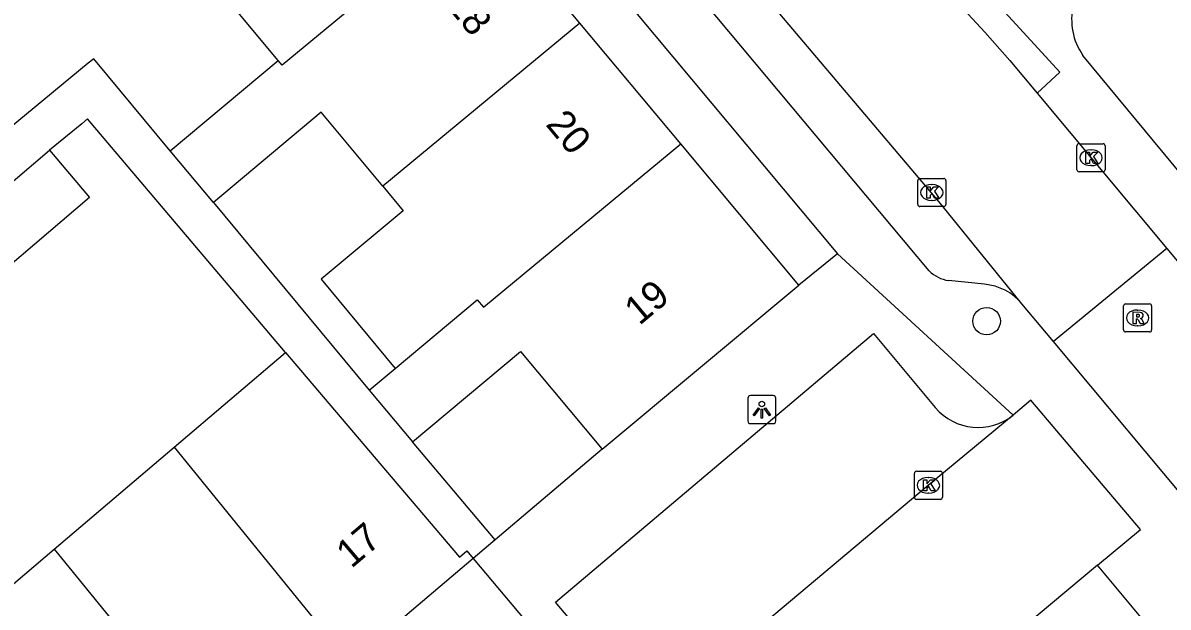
# Model space of a CAD drawing. Extents: x 160379 to 161131, y 383940 to 384849.
# Drawn here: x 160767.81 to 160808.59, y 384435.36 to 384456.14 of the extents above; entities that cross this region are included whole.
import ezdxf

# ---------------------------------------------------------------- set-up
doc = ezdxf.new("R2010")
doc.units = 0
for name, color, linetype in [('IMGEO_Boom', 7, 'Continuous'), ('IMGEO_Kolk', 7, 'Continuous'), ('IMGEO_Lichtpunt', 7, 'Continuous'), ('IMGEO_Muur', 7, 'Continuous'), ('IMGEO_Pand', 7, 'Continuous'), ('IMGEO_Pand_nummerreeks', 7, 'Continuous'), ('IMGEO_Rijbaan_lokaal_open', 7, 'Continuous'), ('IMGEO_Rioolput', 7, 'Continuous'), ('IMGEO_Voetpad_open', 7, 'Continuous')]:
    doc.layers.add(name, color=color, linetype=linetype)

msp = doc.modelspace()

# ---------------------------------------------------------------- linework, layer by layer
at = {"layer": 'IMGEO_Boom'}
msp.add_circle((160802.132, 384445.529), 0.489, dxfattribs=at)
at = {"layer": 'IMGEO_Kolk'}
for p, q in [((160805.349, 384450.917), (160805.349, 384451.769)), ((160805.424, 384451.843), (160806.276, 384451.843)), ((160806.35, 384451.769), (160806.35, 384450.917)), ((160805.837, 384451.623), (160805.862, 384451.623)), ((160805.86, 384451.063), (160805.835, 384451.063)), ((160799.68, 384449.681), (160799.68, 384450.533)), ((160799.755, 384450.607), (160800.607, 384450.607)), ((160800.681, 384450.533), (160800.681, 384449.681)), ((160806.276, 384450.843), (160805.424, 384450.843)), ((160800.168, 384450.387), (160800.193, 384450.387)), ((160800.191, 384449.827), (160800.166, 384449.827)), ((160800.607, 384449.607), (160799.755, 384449.607)), ((160799.558, 384439.264), (160799.558, 384440.116)), ((160799.633, 384440.19), (160800.485, 384440.19)), ((160800.046, 384439.97), (160800.071, 384439.97)), ((160800.559, 384440.116), (160800.559, 384439.264)), ((160800.485, 384439.19), (160799.633, 384439.19)), ((160800.069, 384439.41), (160800.044, 384439.41))]:
    msp.add_line(p, q, dxfattribs=at)
for points in [[(160805.349, 384450.917), (160805.349, 384451.769)], [(160805.424, 384451.843), (160806.276, 384451.843)], [(160806.35, 384451.769), (160806.35, 384450.917)], [(160805.67, 384451.543), (160805.793, 384451.543), (160805.793, 384451.392), (160805.923, 384451.543), (160806.087, 384451.543), (160805.941, 384451.392), (160806.094, 384451.143), (160805.942, 384451.143), (160805.857, 384451.307), (160805.793, 384451.24), (160805.793, 384451.143), (160805.67, 384451.143), (160805.67, 384451.543)], [(160799.68, 384449.681), (160799.68, 384450.533)], [(160799.755, 384450.607), (160800.607, 384450.607)], [(160800.681, 384450.533), (160800.681, 384449.681)], [(160806.276, 384450.843), (160805.424, 384450.843)], [(160800.001, 384450.307), (160800.124, 384450.307), (160800.124, 384450.156), (160800.254, 384450.307), (160800.418, 384450.307), (160800.272, 384450.156), (160800.425, 384449.907), (160800.273, 384449.907), (160800.188, 384450.071), (160800.124, 384450.004), (160800.124, 384449.907), (160800.001, 384449.907), (160800.001, 384450.307)], [(160800.607, 384449.607), (160799.755, 384449.607)], [(160799.558, 384439.264), (160799.558, 384440.116)], [(160799.633, 384440.19), (160800.485, 384440.19)], [(160799.879, 384439.89), (160800.002, 384439.89), (160800.002, 384439.739), (160800.132, 384439.89), (160800.296, 384439.89), (160800.15, 384439.739), (160800.303, 384439.49), (160800.151, 384439.49), (160800.066, 384439.654), (160800.002, 384439.587), (160800.002, 384439.49), (160799.879, 384439.49), (160799.879, 384439.89)], [(160800.559, 384440.116), (160800.559, 384439.264)], [(160800.485, 384439.19), (160799.633, 384439.19)]]:
    msp.add_lwpolyline(points, dxfattribs=at)
for centre, start, end in [((160805.426, 384451.767), 91.552, 178.448), ((160805.426, 384451.767), 91.552, 178.448), ((160806.274, 384451.767), 1.552, 88.448), ((160806.274, 384451.767), 1.552, 88.448), ((160805.426, 384450.919), 181.552, 268.448), ((160805.426, 384450.919), 181.552, 268.448), ((160806.274, 384450.919), 271.552, 358.448), ((160806.274, 384450.919), 271.552, 358.448), ((160799.757, 384450.531), 91.552, 178.448), ((160799.757, 384450.531), 91.552, 178.448), ((160800.605, 384450.531), 1.552, 88.448), ((160800.605, 384450.531), 1.552, 88.448), ((160799.757, 384449.683), 181.552, 268.448), ((160799.757, 384449.683), 181.552, 268.448), ((160800.605, 384449.683), 271.552, 358.448), ((160800.605, 384449.683), 271.552, 358.448), ((160799.635, 384440.114), 91.552, 178.448), ((160799.635, 384440.114), 91.552, 178.448), ((160800.483, 384440.114), 1.552, 88.448), ((160800.483, 384440.114), 1.552, 88.448), ((160799.635, 384439.266), 181.552, 268.448), ((160799.635, 384439.266), 181.552, 268.448), ((160800.483, 384439.266), 271.552, 358.448), ((160800.483, 384439.266), 271.552, 358.448)]:
    msp.add_arc(centre, 0.0765, start, end, dxfattribs=at)
for centre, major_axis, ratio, start_param, end_param in [((160805.836, 384451.343), (-0.387, 0.002), 0.722429, 4.712389, 7.853982), ((160805.861, 384451.343), (-0.39, 0.002), 0.717154, 1.570796, 4.712389), ((160800.167, 384450.107), (-0.387, 0.002), 0.722429, 4.712389, 7.853982), ((160800.192, 384450.107), (-0.39, 0.002), 0.717154, 1.570796, 4.712389), ((160800.045, 384439.69), (-0.387, 0.002), 0.722429, 4.712389, 7.853982), ((160800.07, 384439.69), (-0.39, 0.002), 0.717154, 1.570796, 4.712389)]:
    msp.add_ellipse(centre, major_axis=major_axis, ratio=ratio, start_param=start_param, end_param=end_param, dxfattribs=at)
at = {"layer": 'IMGEO_Lichtpunt'}
for p, q in [((160793.628, 384442.785), (160793.628, 384441.978)), ((160793.628, 384442.785), (160793.628, 384441.978)), ((160794.53, 384442.88), (160793.722, 384442.88)), ((160794.53, 384442.88), (160793.722, 384442.88)), ((160794.624, 384441.978), (160794.624, 384442.785)), ((160794.624, 384441.978), (160794.624, 384442.785)), ((160793.722, 384441.884), (160794.53, 384441.884)), ((160793.722, 384441.884), (160794.53, 384441.884))]:
    msp.add_line(p, q, dxfattribs=at)
for points in [[(160794.002, 384442.449), (160794.041, 384442.421), (160793.853, 384442.159), (160793.815, 384442.186), (160794.002, 384442.449)], [(160794.104, 384442.401), (160794.151, 384442.401), (160794.151, 384442.079), (160794.104, 384442.079), (160794.104, 384442.401)], [(160794.214, 384442.421), (160794.252, 384442.448), (160794.439, 384442.186), (160794.4, 384442.158), (160794.214, 384442.421)]]:
    msp.add_lwpolyline(points, dxfattribs=at)
msp.add_circle((160794.127, 384442.583), 0.0994, dxfattribs=at)
for centre, start, end in [((160793.722, 384442.785), 90, 180), ((160793.722, 384442.785), 90, 180), ((160794.53, 384442.785), 0, 90), ((160794.53, 384442.785), 0, 90), ((160793.722, 384441.978), 180, 270), ((160793.722, 384441.978), 180, 270), ((160794.53, 384441.978), 270, 0), ((160794.53, 384441.978), 270, 360)]:
    msp.add_arc(centre, 0.0946, start, end, dxfattribs=at)
at = {"layer": 'IMGEO_Muur'}
msp.add_lwpolyline([(160788.444, 384440.97), (160783.847, 384437.088)], dxfattribs=at)
at = {"layer": 'IMGEO_Pand'}
for points in [[(160784.057, 384460.433), (160777.042, 384454.637), (160776.901, 384454.807)], [(160787.649, 384456.136), (160784.057, 384460.433)], [(160776.901, 384454.807), (160775.531, 384456.451), (160774.073, 384458.201)], [(160787.649, 384456.136), (160780.627, 384450.335)], [(160791.241, 384451.84), (160787.649, 384456.136)], [(160773.059, 384451.591), (160776.901, 384454.807)], [(160780.627, 384450.335), (160778.437, 384452.963), (160774.595, 384449.747)], [(160781.074, 384443.851), (160783.992, 384446.294), (160784.211, 384446.032), (160791.241, 384451.84)], [(160795.445, 384446.811), (160791.241, 384451.84)], [(160765.333, 384448.701), (160768.754, 384451.607)], [(160768.754, 384451.607), (160770.182, 384449.926), (160766.761, 384447.02)], [(160774.595, 384449.747), (160773.059, 384451.591)], [(160780.627, 384450.335), (160781.355, 384449.46), (160778.431, 384447.025), (160781.074, 384443.851)], [(160788.444, 384440.97), (160795.445, 384446.811)], [(160773.195, 384441.044), (160777.166, 384444.415)], [(160777.166, 384444.415), (160780.118, 384440.94), (160783.355, 384437.129), (160783.621, 384437.355), (160783.847, 384437.088)], [(160781.688, 384441.235), (160785.53, 384444.451), (160788.444, 384440.97)], [(160780.147, 384443.075), (160781.074, 384443.851)], [(160780.147, 384443.075), (160781.688, 384441.235)], [(160768.925, 384437.418), (160773.195, 384441.044)], [(160773.195, 384441.044), (160779.46, 384433.363)], [(160764.656, 384433.793), (160768.925, 384437.418)], [(160768.925, 384437.418), (160775.19, 384429.737)], [(160783.847, 384437.088), (160779.46, 384433.363)]]:
    msp.add_lwpolyline(points, dxfattribs=at)
at = {"layer": 'IMGEO_Rijbaan_lokaal_open'}
for points in [[(160803.39, 384446.147), (160800.426, 384449.782), (160793.188, 384458.339), (160781.229, 384472.652), (160768.71, 384487.604), (160763.66, 384493.663), (160761.152, 384496.606)], [(160789.055, 384469.866), (160802.072, 384455.813), (160802.953, 384454.808), (160803.93, 384453.643)], [(160803.93, 384453.643), (160808.551, 384448.118)], [(160808.551, 384448.118), (160804.509, 384444.81)], [(160808.551, 384448.118), (160813.808, 384441.834)], [(160804.509, 384444.81), (160803.39, 384446.147)], [(160809.774, 384438.517), (160804.509, 384444.81)], [(160806.084, 384436.845), (160807.612, 384438.122), (160803.711, 384442.716), (160803.081, 384442.184)], [(160803.081, 384442.184), (160800.055, 384439.689), (160791.433, 384432.444), (160790.223, 384431.451)], [(160806.084, 384436.845), (160793.999, 384426.749), (160792.832, 384428.202)]]:
    msp.add_lwpolyline(points, dxfattribs=at)
at = {"layer": 'IMGEO_Rioolput'}
for p, q in [((160807.007, 384445.219), (160807.007, 384446.071)), ((160807.082, 384446.145), (160807.934, 384446.145)), ((160808.008, 384446.071), (160808.008, 384445.219)), ((160807.495, 384445.925), (160807.52, 384445.925)), ((160807.518, 384445.365), (160807.493, 384445.365)), ((160807.934, 384445.145), (160807.082, 384445.145))]:
    msp.add_line(p, q, dxfattribs=at)
for points in [[(160807.007, 384445.219), (160807.007, 384446.071)], [(160807.082, 384446.145), (160807.934, 384446.145)], [(160808.008, 384446.071), (160808.008, 384445.219)], [(160807.596, 384445.843), (160807.344, 384445.845), (160807.344, 384445.445)], [(160807.344, 384445.445), (160807.468, 384445.445), (160807.468, 384445.607), (160807.479, 384445.607)], [(160807.522, 384445.764), (160807.468, 384445.764), (160807.468, 384445.683)], [(160807.468, 384445.683), (160807.52, 384445.683)], [(160807.526, 384445.578), (160807.597, 384445.445), (160807.737, 384445.445), (160807.672, 384445.571)], [(160807.934, 384445.145), (160807.082, 384445.145)]]:
    msp.add_lwpolyline(points, dxfattribs=at)
for centre, radius, start, end in [((160807.084, 384446.069), 0.0765, 91.552, 178.448), ((160807.084, 384446.069), 0.0765, 91.552, 178.448), ((160807.932, 384446.069), 0.0765, 1.552, 88.448), ((160807.932, 384446.069), 0.0765, 1.552, 88.448), ((160807.478, 384445.554), 0.0533, 26.0293, 88.6989), ((160807.504, 384445.872), 0.19, 274.7715, 282.9687), ((160807.528, 384445.668), 0.0964, 77.0061, 93.1865), ((160807.542, 384445.725), 0.0378, 276.6634, 79.6772), ((160807.595, 384445.733), 0.109, 350.3612, 89.416), ((160807.593, 384445.733), 0.112, 277.5842, 350.9817), ((160807.577, 384445.518), 0.108, 29.5134, 73.7905), ((160807.084, 384445.221), 0.0765, 181.552, 268.448), ((160807.084, 384445.221), 0.0765, 181.552, 268.448), ((160807.932, 384445.221), 0.0765, 271.552, 358.448), ((160807.932, 384445.221), 0.0765, 271.552, 358.448)]:
    msp.add_arc(centre, radius, start, end, dxfattribs=at)
for centre, major_axis, ratio, start_param, end_param in [((160807.494, 384445.645), (-0.387, 0.002), 0.722429, 4.712389, 7.853982), ((160807.519, 384445.645), (-0.39, 0.002), 0.717154, 1.570796, 4.712389)]:
    msp.add_ellipse(centre, major_axis=major_axis, ratio=ratio, start_param=start_param, end_param=end_param, dxfattribs=at)
at = {"layer": 'IMGEO_Voetpad_open'}
for points in [[(160755.214, 384497.645), (160796.819, 384447.928)], [(160789.055, 384469.866), (160789.866, 384470.61), (160804.741, 384454.387), (160803.93, 384453.643)], [(160800.083, 384447.315), (160785.822, 384464.362), (160785.692, 384465.126), (160785.822, 384466.096)], [(160812.823, 384446.222), (160805.559, 384454.985)], [(160773.059, 384451.591), (160770.334, 384454.863), (160770.141, 384454.703), (160757.907, 384444.611), (160757.049, 384445.651)], [(160777.166, 384444.415), (160770.109, 384452.722), (160769.906, 384452.55), (160768.754, 384451.607)], [(160774.595, 384449.747), (160780.147, 384443.075)], [(160796.819, 384447.928), (160795.445, 384446.811)], [(160803.081, 384442.184), (160796.819, 384447.928)], [(160802.056, 384446.84), (160800.775, 384446.976)], [(160790.223, 384431.451), (160786.779, 384435.536), (160798.106, 384445.096), (160800.301, 384442.454)], [(160784.631, 384437.75), (160781.688, 384441.235)], [(160788.444, 384440.97), (160784.631, 384437.75)], [(160784.631, 384437.75), (160783.847, 384437.088)], [(160783.847, 384437.088), (160786.412, 384434.035), (160772.059, 384421.878)], [(160807.803, 384434.788), (160806.084, 384436.845)]]:
    msp.add_lwpolyline(points, dxfattribs=at)
for centre, radius, start, end in [((160807.355, 384456.25), 2.196, 118.0132, 215.1631), ((160800.965, 384448.239), 1.278, 226.3477, 261.4532), ((160801.904, 384444.918), 1.928, 39.6084, 85.4887), ((160801.832, 384443.768), 2.017, 220.6388, 308.2666)]:
    msp.add_arc(centre, radius, start, end, dxfattribs=at)

# ---------------------------------------------------------------- texts
at = {"layer": 'IMGEO_Pand_nummerreeks'}
for s, rotation, p in [('18', 309.8973, (160782.866, 384456.743)), ('20', 309.8948, (160786.4, 384452.517)), ('19', 39.8378, (160789.765, 384445.354)), ('17', 40.3347, (160779.508, 384436.71))]:
    msp.add_text(s, height=1, rotation=rotation, dxfattribs=at).set_placement(p)

doc.saveas('drawing.dxf')
